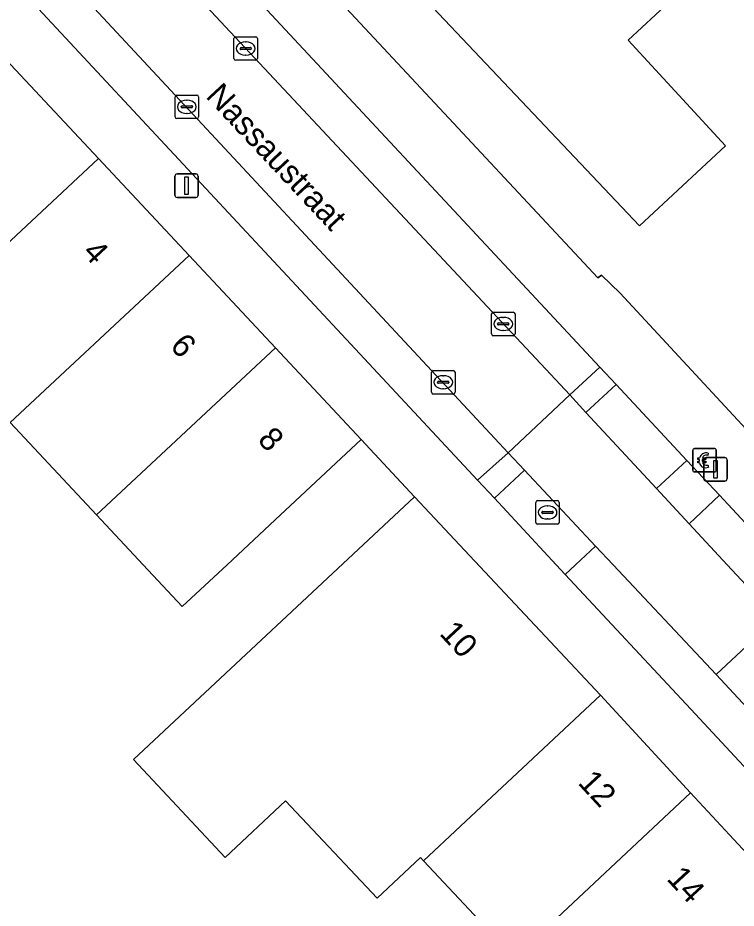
# Model space of a CAD drawing. Extents: x 159960 to 160866, y 382700 to 383354.
# Drawn here: x 160677.38 to 160707.93, y 382985.38 to 383023.28 of the extents above; entities that cross this region are included whole.
import ezdxf

# ---------------------------------------------------------------- set-up
doc = ezdxf.new("R2010")
doc.units = 0
for name, color, linetype in [('IMGEO_Betaalautomaat', 7, 'Continuous'), ('IMGEO_Erf', 7, 'Continuous'), ('IMGEO_Kolk', 7, 'Continuous'), ('IMGEO_Lichtmast', 7, 'Continuous'), ('IMGEO_Openbare_ruimte_label', 7, 'Continuous'), ('IMGEO_Pand', 7, 'Continuous'), ('IMGEO_Pand_nummerreeks', 7, 'Continuous'), ('IMGEO_Parkeervlak_open', 7, 'Continuous'), ('IMGEO_Rijbaan_lokaal_open', 7, 'Continuous'), ('IMGEO_Rioolput', 7, 'Continuous'), ('IMGEO_Voetpad_open', 7, 'Continuous')]:
    doc.layers.add(name, color=color, linetype=linetype)

msp = doc.modelspace()

# ---------------------------------------------------------------- linework, layer by layer
at = {"layer": 'IMGEO_Betaalautomaat'}
for p, q in [((160706.158, 383004.947), (160706.999, 383004.947)), ((160706.999, 383004.947), (160706.158, 383004.947)), ((160706.083, 383004.023), (160706.083, 383004.864)), ((160706.083, 383004.864), (160706.083, 383004.023)), ((160706.745, 383004.752), (160706.728, 383004.652)), ((160707.082, 383004.873), (160707.082, 383004.032)), ((160707.082, 383004.032), (160707.082, 383004.873)), ((160706.366, 383004.411), (160706.366, 383004.479)), ((160706.487, 383004.479), (160706.487, 383004.411)), ((160706.732, 383004.246), (160706.754, 383004.159)), ((160707.008, 383003.948), (160706.167, 383003.948)), ((160706.167, 383003.948), (160707.008, 383003.948))]:
    msp.add_line(p, q, dxfattribs=at)
for points in [[(160706.366, 383004.479), (160706.297, 383004.479), (160706.297, 383004.548), (160706.376, 383004.548)], [(160706.498, 383004.548), (160706.645, 383004.548), (160706.645, 383004.479), (160706.487, 383004.479)], [(160706.371, 383004.342), (160706.297, 383004.342), (160706.297, 383004.411), (160706.366, 383004.411)], [(160706.487, 383004.411), (160706.645, 383004.411), (160706.645, 383004.342), (160706.501, 383004.342)]]:
    msp.add_lwpolyline(points, dxfattribs=at)
for centre, radius, start, end in [((160706.161, 383004.87), 0.0779, 92.4484, 184.2845), ((160706.161, 383004.87), 0.0779, 92.4484, 184.2845), ((160707.005, 383004.87), 0.0779, 2.4484, 94.2845), ((160707.005, 383004.87), 0.0779, 2.4484, 94.2845), ((160706.659, 383004.472), 0.293, 73.014, 165.0139), ((160706.665, 383004.485), 0.179, 69.3236, 159.5683), ((160706.632, 383004.397), 0.267, 191.8096, 297.0389), ((160706.665, 383004.412), 0.179, 202.7625, 291.8693), ((160706.161, 383004.026), 0.0779, 182.4484, 274.2845), ((160706.161, 383004.026), 0.0779, 182.4484, 274.2845), ((160707.005, 383004.026), 0.0779, 272.4484, 4.2845), ((160707.005, 383004.026), 0.0779, 272.4484, 4.2845)]:
    msp.add_arc(centre, radius, start, end, dxfattribs=at)
at = {"layer": 'IMGEO_Erf'}
for points in [[(160673.235, 383043.388), (160678.604, 383037.664), (160678.452, 383037.535), (160702.049, 383012.215), (160702.21, 383012.323), (160702.992, 383011.556), (160713.702, 383000), (160739.609, 382972.048)], [(160698.5, 382983.267), (160694.63, 382987.392), (160694.499, 382987.531), (160692.655, 382985.801), (160688.767, 382989.956), (160686.19, 382987.544), (160682.295, 382991.706), (160694.256, 383002.897), (160691.981, 383005.329), (160688.328, 383001.916), (160686.276, 383000), (160684.373, 382998.223), (160682.713, 383000), (160680.724, 383002.128), (160677.05, 383006.06)]]:
    msp.add_lwpolyline(points, dxfattribs=at)
msp.add_lwpolyline([(160707.478, 383017.834), (160703.819, 383014.425), (160692.261, 383026.655), (160689.572, 383029.501), (160689.725, 383029.643), (160680.92, 383039.091), (160684.485, 383042.414), (160688.57, 383037.978), (160690.403, 383039.686), (160695.005, 383034.747), (160696.144, 383035.809), (160698.86, 383032.895), (160701.574, 383029.983), (160700.438, 383028.924), (160705.076, 383023.947), (160703.339, 383022.328)], close=True, dxfattribs=at)
at = {"layer": 'IMGEO_Kolk'}
for p, q in [((160686.57, 383021.55), (160686.57, 383022.402)), ((160686.645, 383022.476), (160687.497, 383022.476)), ((160687.571, 383022.402), (160687.571, 383021.55)), ((160686.829, 383021.97), (160686.829, 383021.982)), ((160686.872, 383022.019), (160687.27, 383022.019)), ((160687.058, 383022.256), (160687.083, 383022.256)), ((160687.313, 383021.982), (160687.313, 383021.97)), ((160687.267, 383021.933), (160686.869, 383021.933)), ((160687.081, 383021.696), (160687.056, 383021.696)), ((160687.497, 383021.476), (160686.645, 383021.476)), ((160684.065, 383019.069), (160684.065, 383019.921)), ((160684.14, 383019.995), (160684.992, 383019.995)), ((160684.553, 383019.775), (160684.578, 383019.775)), ((160685.066, 383019.921), (160685.066, 383019.069)), ((160684.324, 383019.489), (160684.324, 383019.501)), ((160684.762, 383019.452), (160684.364, 383019.452)), ((160684.367, 383019.538), (160684.765, 383019.538)), ((160684.808, 383019.501), (160684.808, 383019.489)), ((160684.992, 383018.995), (160684.14, 383018.995)), ((160684.576, 383019.215), (160684.551, 383019.215)), ((160697.525, 383009.824), (160697.525, 383010.676)), ((160697.6, 383010.75), (160698.452, 383010.75)), ((160698.526, 383010.676), (160698.526, 383009.824)), ((160697.784, 383010.244), (160697.784, 383010.256)), ((160698.222, 383010.207), (160697.824, 383010.207)), ((160697.827, 383010.293), (160698.225, 383010.293)), ((160698.013, 383010.53), (160698.038, 383010.53)), ((160698.268, 383010.256), (160698.268, 383010.244)), ((160698.036, 383009.97), (160698.011, 383009.97)), ((160698.452, 383009.75), (160697.6, 383009.75)), ((160694.972, 383007.342), (160694.972, 383008.194)), ((160695.047, 383008.268), (160695.899, 383008.268)), ((160695.46, 383008.048), (160695.485, 383008.048)), ((160695.973, 383008.194), (160695.973, 383007.342)), ((160695.231, 383007.762), (160695.231, 383007.774)), ((160695.669, 383007.725), (160695.271, 383007.725)), ((160695.274, 383007.811), (160695.672, 383007.811)), ((160695.715, 383007.774), (160695.715, 383007.762)), ((160695.899, 383007.268), (160695.047, 383007.268)), ((160695.483, 383007.488), (160695.458, 383007.488))]:
    msp.add_line(p, q, dxfattribs=at)
for points in [[(160686.57, 383021.55), (160686.57, 383022.402)], [(160686.645, 383022.476), (160687.497, 383022.476)], [(160687.571, 383022.402), (160687.571, 383021.55)], [(160687.497, 383021.476), (160686.645, 383021.476)], [(160684.065, 383019.069), (160684.065, 383019.921)], [(160684.14, 383019.995), (160684.992, 383019.995)], [(160685.066, 383019.921), (160685.066, 383019.069)], [(160684.992, 383018.995), (160684.14, 383018.995)], [(160697.525, 383009.824), (160697.525, 383010.676)], [(160697.6, 383010.75), (160698.452, 383010.75)], [(160698.526, 383010.676), (160698.526, 383009.824)], [(160698.452, 383009.75), (160697.6, 383009.75)], [(160694.972, 383007.342), (160694.972, 383008.194)], [(160695.047, 383008.268), (160695.899, 383008.268)], [(160695.973, 383008.194), (160695.973, 383007.342)], [(160695.899, 383007.268), (160695.047, 383007.268)]]:
    msp.add_lwpolyline(points, dxfattribs=at)
for centre, radius, start, end in [((160686.647, 383022.4), 0.0765, 91.552, 178.448), ((160686.647, 383022.4), 0.0765, 91.552, 178.448), ((160687.495, 383022.4), 0.0765, 1.552, 88.448), ((160687.495, 383022.4), 0.0765, 1.552, 88.448), ((160686.869, 383021.979), 0.0403, 85.8775, 175.7526), ((160686.866, 383021.969), 0.0366, 178.938, 274.7102), ((160687.27, 383021.976), 0.043, 264.8664, 352.4533), ((160687.274, 383021.981), 0.0386, 1.7309, 96.639), ((160686.647, 383021.552), 0.0765, 181.552, 268.448), ((160686.647, 383021.552), 0.0765, 181.552, 268.448), ((160687.495, 383021.552), 0.0765, 271.552, 358.448), ((160687.495, 383021.552), 0.0765, 271.552, 358.448), ((160684.142, 383019.919), 0.0765, 91.552, 178.448), ((160684.142, 383019.919), 0.0765, 91.552, 178.448), ((160684.99, 383019.919), 0.0765, 1.552, 88.448), ((160684.99, 383019.919), 0.0765, 1.552, 88.448), ((160684.364, 383019.498), 0.0403, 85.8775, 175.7526), ((160684.361, 383019.488), 0.0366, 178.938, 274.7102), ((160684.765, 383019.495), 0.043, 264.8664, 352.4533), ((160684.769, 383019.5), 0.0386, 1.7309, 96.639), ((160684.142, 383019.071), 0.0765, 181.552, 268.448), ((160684.142, 383019.071), 0.0765, 181.552, 268.448), ((160684.99, 383019.071), 0.0765, 271.552, 358.448), ((160684.99, 383019.071), 0.0765, 271.552, 358.448), ((160697.602, 383010.674), 0.0765, 91.552, 178.448), ((160697.602, 383010.674), 0.0765, 91.552, 178.448), ((160698.45, 383010.674), 0.0765, 1.552, 88.448), ((160698.45, 383010.674), 0.0765, 1.552, 88.448), ((160697.824, 383010.253), 0.0403, 85.8775, 175.7526), ((160697.821, 383010.243), 0.0366, 178.938, 274.7102), ((160698.225, 383010.25), 0.043, 264.8664, 352.4533), ((160698.229, 383010.255), 0.0386, 1.7309, 96.639), ((160697.602, 383009.826), 0.0765, 181.552, 268.448), ((160697.602, 383009.826), 0.0765, 181.552, 268.448), ((160698.45, 383009.826), 0.0765, 271.552, 358.448), ((160698.45, 383009.826), 0.0765, 271.552, 358.448), ((160695.049, 383008.192), 0.0765, 91.552, 178.448), ((160695.049, 383008.192), 0.0765, 91.552, 178.448), ((160695.897, 383008.192), 0.0765, 1.552, 88.448), ((160695.897, 383008.192), 0.0765, 1.552, 88.448), ((160695.271, 383007.771), 0.0403, 85.8775, 175.7526), ((160695.268, 383007.761), 0.0366, 178.938, 274.7102), ((160695.672, 383007.768), 0.043, 264.8664, 352.4533), ((160695.676, 383007.773), 0.0386, 1.7309, 96.639), ((160695.049, 383007.344), 0.0765, 181.552, 268.448), ((160695.049, 383007.344), 0.0765, 181.552, 268.448), ((160695.897, 383007.344), 0.0765, 271.552, 358.448), ((160695.897, 383007.344), 0.0765, 271.552, 358.448)]:
    msp.add_arc(centre, radius, start, end, dxfattribs=at)
for centre, major_axis, ratio, start_param, end_param in [((160687.057, 383021.976), (-0.387, 0.002), 0.722429, 4.712389, 7.853982), ((160687.082, 383021.976), (-0.39, 0.002), 0.717154, 1.570796, 4.712389), ((160684.552, 383019.495), (-0.387, 0.002), 0.722429, 4.712389, 7.853982), ((160684.577, 383019.495), (-0.39, 0.002), 0.717154, 1.570796, 4.712389), ((160698.012, 383010.25), (-0.387, 0.002), 0.722429, 4.712389, 7.853982), ((160698.037, 383010.25), (-0.39, 0.002), 0.717154, 1.570796, 4.712389), ((160695.459, 383007.768), (-0.387, 0.002), 0.722429, 4.712389, 7.853982), ((160695.484, 383007.768), (-0.39, 0.002), 0.717154, 1.570796, 4.712389)]:
    msp.add_ellipse(centre, major_axis=major_axis, ratio=ratio, start_param=start_param, end_param=end_param, dxfattribs=at)
at = {"layer": 'IMGEO_Lichtmast'}
for p, q in [((160684.158, 383016.635), (160684.948, 383016.635)), ((160684.948, 383016.635), (160684.158, 383016.635)), ((160684.058, 383015.735), (160684.058, 383016.535)), ((160684.058, 383016.535), (160684.058, 383015.735)), ((160685.048, 383016.535), (160685.048, 383015.735)), ((160685.048, 383015.735), (160685.048, 383016.535)), ((160684.948, 383015.635), (160684.158, 383015.635)), ((160684.158, 383015.635), (160684.948, 383015.635)), ((160706.656, 383004.561), (160707.446, 383004.561)), ((160707.446, 383004.561), (160706.656, 383004.561)), ((160706.556, 383003.661), (160706.556, 383004.461)), ((160706.556, 383004.461), (160706.556, 383003.661)), ((160707.546, 383004.461), (160707.546, 383003.661)), ((160707.546, 383003.661), (160707.546, 383004.461)), ((160707.446, 383003.561), (160706.656, 383003.561)), ((160706.656, 383003.561), (160707.446, 383003.561))]:
    msp.add_line(p, q, dxfattribs=at)
for points in [[(160684.478, 383016.51), (160684.628, 383016.51), (160684.628, 383015.76), (160684.478, 383015.76), (160684.478, 383016.51)], [(160706.976, 383004.436), (160707.126, 383004.436), (160707.126, 383003.686), (160706.976, 383003.686), (160706.976, 383004.436)]]:
    msp.add_lwpolyline(points, dxfattribs=at)
for centre, start, end in [((160684.158, 383016.535), 90, 180), ((160684.158, 383016.535), 90, 180), ((160684.948, 383016.535), 0, 90), ((160684.948, 383016.535), 360, 90), ((160684.158, 383015.735), 180, 270), ((160684.158, 383015.735), 180, 270), ((160684.948, 383015.735), 270, 0), ((160684.948, 383015.735), 270, 0), ((160706.656, 383004.461), 90, 180), ((160706.656, 383004.461), 90, 180), ((160707.446, 383004.461), 0, 90), ((160707.446, 383004.461), 360, 90), ((160706.656, 383003.661), 180, 270), ((160706.656, 383003.661), 180, 270), ((160707.446, 383003.661), 270, 0), ((160707.446, 383003.661), 270, 0)]:
    msp.add_arc(centre, 0.1, start, end, dxfattribs=at)
at = {"layer": 'IMGEO_Pand'}
for points in [[(160698.86, 383032.895), (160692.261, 383026.655), (160703.819, 383014.425), (160707.478, 383017.834), (160703.339, 383022.328), (160705.076, 383023.947), (160700.438, 383028.924), (160701.574, 383029.983)], [(160674.164, 383024.406), (160672.895, 383023.211), (160670.995, 383021.462), (160670.045, 383020.56), (160675.072, 383015.177), (160672.17, 383012.468), (160673.028, 383011.549), (160673.788, 383010.736), (160680.806, 383017.294)], [(160684.661, 383013.167), (160680.806, 383017.294), (160673.788, 383010.736), (160673.242, 383010.135), (160677.05, 383006.06)], [(160684.661, 383013.167), (160677.05, 383006.06), (160680.724, 383002.128), (160688.333, 383009.235)], [(160680.724, 383002.128), (160682.713, 383000), (160684.373, 382998.223), (160686.276, 383000), (160688.328, 383001.916), (160691.981, 383005.329), (160688.333, 383009.235)], [(160694.256, 383002.897), (160682.295, 382991.706), (160686.19, 382987.544), (160688.767, 382989.956), (160692.655, 382985.801), (160694.499, 382987.531), (160694.63, 382987.392), (160696.201, 382988.866), (160702.157, 382994.453)], [(160696.201, 382988.866), (160694.63, 382987.392), (160698.5, 382983.267), (160705.995, 382990.297), (160702.157, 382994.453)], [(160702.288, 382979.229), (160709.309, 382985.813), (160708.406, 382986.786), (160708.387, 382987.707), (160705.995, 382990.297), (160698.5, 382983.267)]]:
    msp.add_lwpolyline(points, close=True, dxfattribs=at)
at = {"layer": 'IMGEO_Parkeervlak_open'}
for points in [[(160672.178, 383037.909), (160700.852, 383007.229), (160702.135, 383008.415), (160675.357, 383037.17)], [(160670.905, 383031.554), (160696.934, 383003.596), (160698.234, 383004.765), (160670.275, 383034.824)], [(160716.257, 382985.452), (160707.076, 382995.331), (160702.7, 383000), (160701.956, 383000.793), (160701.104, 383000), (160700.664, 382999.59), (160706.009, 382993.847), (160713.29, 382985.999)]]:
    msp.add_lwpolyline(points, dxfattribs=at)
for points in [[(160704.544, 383003.244), (160705.84, 383004.437), (160702.829, 383007.669), (160701.543, 383006.483)], [(160697.65, 383002.827), (160700.282, 383000), (160700.664, 382999.59), (160701.104, 383000), (160701.956, 383000.793), (160698.922, 383004.029)], [(160705.933, 383001.745), (160707.55, 383000), (160708.935, 382998.505), (160710.24, 382999.711), (160709.971, 383000), (160707.217, 383002.958)]]:
    msp.add_lwpolyline(points, close=True, dxfattribs=at)
at = {"layer": 'IMGEO_Rijbaan_lokaal_open'}
for points in [[(160670.275, 383034.824), (160698.234, 383004.765), (160700.852, 383007.229), (160672.178, 383037.909)], [(160734.313, 382971.169), (160733.364, 382972.191), (160709.652, 382997.732), (160707.076, 382995.331), (160716.257, 382985.452), (160717.644, 382983.994), (160725.867, 382975.173), (160729.198, 382971.599)]]:
    msp.add_lwpolyline(points, dxfattribs=at)
msp.add_lwpolyline([(160705.933, 383001.745), (160704.544, 383003.244), (160701.543, 383006.483), (160700.852, 383007.229), (160698.234, 383004.765), (160698.922, 383004.029), (160701.956, 383000.793), (160702.7, 383000), (160707.076, 382995.331), (160709.652, 382997.732), (160708.935, 382998.505), (160707.55, 383000)], close=True, dxfattribs=at)
at = {"layer": 'IMGEO_Rioolput'}
for p, q in [((160699.409, 383001.803), (160699.409, 383002.655)), ((160699.484, 383002.729), (160700.336, 383002.729)), ((160700.41, 383002.655), (160700.41, 383001.803)), ((160699.668, 383002.223), (160699.668, 383002.235)), ((160699.711, 383002.272), (160700.109, 383002.272)), ((160699.897, 383002.509), (160699.922, 383002.509)), ((160700.152, 383002.235), (160700.152, 383002.223)), ((160700.106, 383002.186), (160699.708, 383002.186)), ((160699.92, 383001.949), (160699.895, 383001.949)), ((160700.336, 383001.729), (160699.484, 383001.729))]:
    msp.add_line(p, q, dxfattribs=at)
for points in [[(160699.409, 383001.803), (160699.409, 383002.655)], [(160699.484, 383002.729), (160700.336, 383002.729)], [(160700.41, 383002.655), (160700.41, 383001.803)], [(160700.336, 383001.729), (160699.484, 383001.729)]]:
    msp.add_lwpolyline(points, dxfattribs=at)
for centre, radius, start, end in [((160699.486, 383002.653), 0.0765, 91.552, 178.448), ((160699.486, 383002.653), 0.0765, 91.552, 178.448), ((160700.334, 383002.653), 0.0765, 1.552, 88.448), ((160700.334, 383002.653), 0.0765, 1.552, 88.448), ((160699.708, 383002.232), 0.0403, 85.8775, 175.7526), ((160700.113, 383002.234), 0.0386, 1.7309, 96.639), ((160699.705, 383002.222), 0.0366, 178.938, 274.7102), ((160700.109, 383002.229), 0.043, 264.8664, 352.4533), ((160699.486, 383001.805), 0.0765, 181.552, 268.448), ((160699.486, 383001.805), 0.0765, 181.552, 268.448), ((160700.334, 383001.805), 0.0765, 271.552, 358.448), ((160700.334, 383001.805), 0.0765, 271.552, 358.448)]:
    msp.add_arc(centre, radius, start, end, dxfattribs=at)
for centre, major_axis, ratio, start_param, end_param in [((160699.896, 383002.229), (-0.387, 0.002), 0.722429, 4.712389, 7.853982), ((160699.921, 383002.229), (-0.39, 0.002), 0.717154, 1.570796, 4.712389)]:
    msp.add_ellipse(centre, major_axis=major_axis, ratio=ratio, start_param=start_param, end_param=end_param, dxfattribs=at)
at = {"layer": 'IMGEO_Voetpad_open'}
for points in [[(160739.609, 382972.048), (160713.702, 383000), (160702.992, 383011.556), (160702.21, 383012.323), (160702.049, 383012.215), (160678.452, 383037.535), (160678.604, 383037.664), (160673.235, 383043.388)], [(160675.357, 383037.17), (160702.135, 383008.415), (160702.829, 383007.669), (160705.84, 383004.437), (160707.217, 383002.958), (160709.971, 383000), (160710.24, 382999.711), (160732.864, 382975.416)], [(160713.29, 382985.999), (160706.009, 382993.847), (160700.664, 382999.59), (160700.282, 383000), (160697.65, 383002.827), (160696.934, 383003.596), (160670.905, 383031.554)], [(160674.164, 383024.406), (160680.806, 383017.294), (160684.661, 383013.167), (160688.333, 383009.235), (160691.981, 383005.329), (160694.256, 383002.897), (160702.157, 382994.453), (160705.995, 382990.297), (160708.387, 382987.707), (160708.406, 382986.786), (160709.309, 382985.813), (160710.214, 382984.848), (160711.038, 382984.809), (160716.681, 382978.726), (160718.793, 382976.44), (160720.853, 382974.209), (160724.596, 382970.181), (160724.486, 382968.87), (160725.074, 382968.708), (160724.51, 382960.63), (160724.4, 382958.802), (160729.476, 382958.258)]]:
    msp.add_lwpolyline(points, dxfattribs=at)
for points in [[(160702.135, 383008.415), (160700.852, 383007.229), (160701.543, 383006.483), (160702.829, 383007.669)], [(160697.65, 383002.827), (160698.922, 383004.029), (160698.234, 383004.765), (160696.934, 383003.596)], [(160705.933, 383001.745), (160707.217, 383002.958), (160705.84, 383004.437), (160704.544, 383003.244)]]:
    msp.add_lwpolyline(points, close=True, dxfattribs=at)

# ---------------------------------------------------------------- texts
at = {"layer": 'IMGEO_Openbare_ruimte_label'}
msp.add_text('Nassaustraat', height=1, rotation=313.0558, dxfattribs=at).set_placement((160685.331, 383019.918))
at = {"layer": 'IMGEO_Pand_nummerreeks'}
for s, rotation, p in [('4', 313.0447, (160680.084, 383013.262)), ('6', 313.0447, (160683.809, 383009.274)), ('8', 313.0447, (160687.537, 383005.283)), ('10', 312.8857, (160695.273, 382997.046)), ('12', 312.7237, (160701.165, 382990.693)), ('14', 312.7237, (160704.94, 382986.606))]:
    msp.add_text(s, height=1, rotation=rotation, dxfattribs=at).set_placement(p)

doc.saveas('drawing.dxf')
